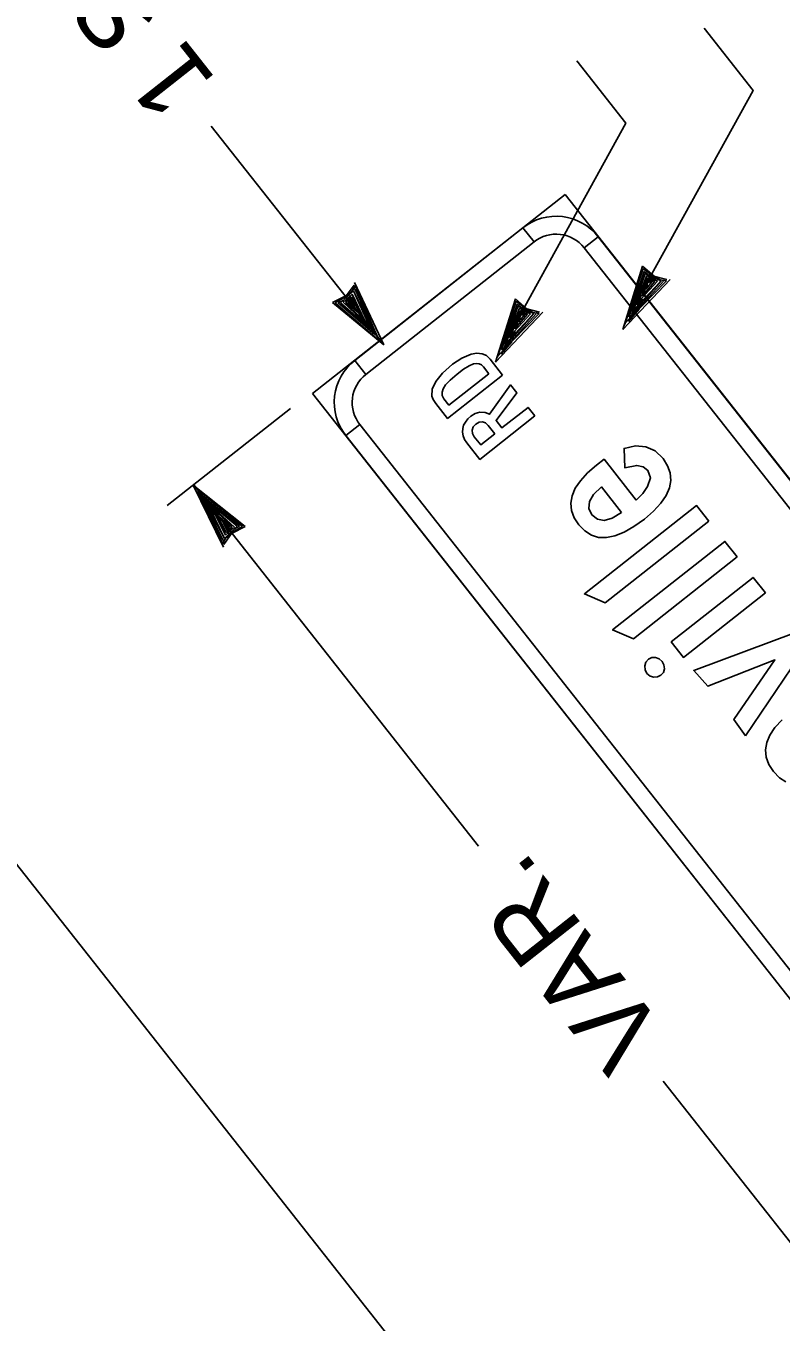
# Model space of a CAD drawing. Extents: x 672438 to 673763, y 1673171 to 1675010.
# Drawn here: x 673288.4 to 673330.7, y 1674719.6 to 1674792.2 of the extents above; entities that cross this region are included whole.
import ezdxf

# ---------------------------------------------------------------- set-up
doc = ezdxf.new("R2010")
doc.units = 0
for name, color, linetype in [('61', 7, 'Continuous'), ('C-ANNO-SYMB', 7, 'Continuous'), ('Level 1', 7, 'Continuous')]:
    doc.layers.add(name, color=color, linetype=linetype)

msp = doc.modelspace()

# ---------------------------------------------------------------- linework, layer by layer
at = {"layer": '61'}
msp.add_lwpolyline([(673330.593, 1674691.063), (673257.062, 1674784.333), (673234.11, 1674766.239), (673307.64, 1674672.968)], close=True, dxfattribs=at)
at = {"layer": 'C-ANNO-SYMB'}
for p, q in [((673318.61, 1674782.748), (673304.474, 1674771.604)), ((673318.61, 1674782.748), (673359.471, 1674730.917)), ((673316.254, 1674780.891), (673316.873, 1674780.105)), ((673319.682, 1674779.773), (673320.467, 1674780.392)), ((673307.449, 1674772.676), (673306.83, 1674773.461)), ((673304.474, 1674771.604), (673345.335, 1674719.774)), ((673306.332, 1674769.248), (673307.117, 1674769.867))]:
    msp.add_line(p, q, dxfattribs=at)
for points in [[(673316.873, 1674780.105), (673307.449, 1674772.676), (673306.83, 1674773.461), (673316.254, 1674780.891), (673316.873, 1674780.105), (673316.873, 1674780.105)], [(673356.828, 1674732.654), (673319.682, 1674779.773), (673320.467, 1674780.392), (673357.613, 1674733.273), (673356.828, 1674732.654), (673356.828, 1674732.654)], [(673307.117, 1674769.867), (673344.263, 1674722.749), (673343.478, 1674722.13), (673306.332, 1674769.248), (673307.117, 1674769.867), (673307.117, 1674769.867)], [(673326.66, 1674764.461), (673325.974, 1674765.33), (673319.692, 1674760.377), (673320.854, 1674759.883)], [(673328.245, 1674762.45), (673327.559, 1674763.32), (673321.277, 1674758.367), (673322.439, 1674757.873)], [(673329.83, 1674760.44), (673329.144, 1674761.309), (673324.553, 1674757.69), (673325.239, 1674756.821)], [(673328.706, 1674752.423), (673332.141, 1674757.508), (673331.568, 1674758.235), (673325.816, 1674756.089), (673326.6, 1674755.207), (673330.366, 1674756.681), (673328.07, 1674753.342)], [(673323.98, 1674755.828), (673324.115, 1674755.986), (673324.171, 1674756.189), (673324.149, 1674756.402), (673324.045, 1674756.596), (673323.879, 1674756.748), (673323.678, 1674756.824), (673323.472, 1674756.817), (673323.279, 1674756.717), (673323.137, 1674756.552), (673323.073, 1674756.346), (673323.093, 1674756.129), (673323.199, 1674755.929), (673323.368, 1674755.78), (673323.577, 1674755.714), (673323.792, 1674755.729)]]:
    msp.add_lwpolyline(points, close=True, dxfattribs=at)
for points in [[(673315.117, 1674772.641), (673314.41, 1674773.538), (673314.21, 1674773.727), (673313.965, 1674773.833), (673313.679, 1674773.859), (673313.347, 1674773.804), (673312.83, 1674773.592), (673312.304, 1674773.243), (673311.746, 1674772.748), (673311.367, 1674772.285), (673311.169, 1674771.857), (673311.15, 1674771.463), (673311.226, 1674771.274), (673311.373, 1674771.054), (673312.037, 1674770.212), (673315.117, 1674772.641)], [(673314.34, 1674772.713), (673312.112, 1674770.957), (673311.828, 1674771.318), (673311.738, 1674771.489), (673311.723, 1674771.674), (673311.784, 1674771.874), (673311.921, 1674772.089), (673312.172, 1674772.353), (673312.576, 1674772.694), (673312.925, 1674772.969), (673313.24, 1674773.164), (673313.481, 1674773.267), (673313.647, 1674773.292), (673313.794, 1674773.271), (673313.926, 1674773.205), (673314.039, 1674773.095), (673314.34, 1674772.713)], [(673316.925, 1674770.348), (673316.544, 1674770.831), (673315.078, 1674769.675), (673314.753, 1674770.086), (673315.902, 1674771.645), (673315.554, 1674772.087), (673314.388, 1674770.443), (673314.13, 1674770.549), (673313.846, 1674770.56), (673313.583, 1674770.487), (673313.336, 1674770.339), (673313.161, 1674770.18), (673313.027, 1674770.009), (673312.933, 1674769.829), (673312.879, 1674769.64), (673312.868, 1674769.437), (673312.905, 1674769.236), (673312.988, 1674769.037), (673313.118, 1674768.841), (673313.845, 1674767.919), (673316.925, 1674770.348)], [(673314.672, 1674769.355), (673313.887, 1674768.736), (673313.53, 1674769.188), (673313.433, 1674769.368), (673313.412, 1674769.557), (673313.474, 1674769.737), (673313.615, 1674769.892), (673313.806, 1674770.003), (673313.983, 1674770.028), (673314.15, 1674769.968), (673314.304, 1674769.822), (673314.672, 1674769.355)], [(673322.596, 1674765.64), (673320.793, 1674767.928), (673320.368, 1674767.593), (673319.868, 1674767.156), (673319.47, 1674766.724), (673319.186, 1674766.298), (673319.006, 1674765.877), (673318.939, 1674765.46), (673318.978, 1674765.05), (673319.129, 1674764.645), (673319.383, 1674764.249), (673319.716, 1674763.908), (673320.084, 1674763.674), (673320.489, 1674763.55), (673320.927, 1674763.537), (673321.407, 1674763.632), (673321.918, 1674763.836), (673322.467, 1674764.149), (673323.053, 1674764.572), (673323.572, 1674765.02), (673323.98, 1674765.461), (673324.278, 1674765.895), (673324.462, 1674766.321), (673324.539, 1674766.74), (673324.502, 1674767.155), (673324.355, 1674767.563), (673324.096, 1674767.961), (673323.651, 1674768.39), (673323.14, 1674768.628), (673322.563, 1674768.676), (673321.918, 1674768.531), (673321.955, 1674767.451), (673322.628, 1674767.579), (673322.985, 1674767.507), (673323.25, 1674767.295), (673323.388, 1674766.892), (673323.231, 1674766.392), (673322.965, 1674766.008), (673322.596, 1674765.64)], [(673321.77, 1674764.949), (673321.253, 1674764.627), (673320.803, 1674764.499), (673320.422, 1674764.562), (673320.109, 1674764.818), (673319.941, 1674765.172), (673319.972, 1674765.552), (673320.208, 1674765.952), (673320.643, 1674766.377), (673321.77, 1674764.949)], [(673330.764, 1674753.335), (673330.367, 1674752.902), (673330.082, 1674752.476), (673329.902, 1674752.056), (673329.835, 1674751.639), (673329.874, 1674751.228), (673330.025, 1674750.824), (673330.279, 1674750.427), (673330.613, 1674750.087), (673330.98, 1674749.853)]]:
    msp.add_lwpolyline(points, dxfattribs=at)
for centre, radius, start, end in [((673318.111, 1674778.535), 3, 38.2506, 128.25081), ((673318.111, 1674778.535), 2, 38.2506, 128.25081), ((673308.688, 1674771.106), 3, 128.25054, 218.25075), ((673308.688, 1674771.106), 2, 128.25054, 218.25075)]:
    msp.add_arc(centre, radius, start, end, dxfattribs=at)
at = {"layer": 'Level 1'}
for p, q in [((673308.457, 1674774.332), (673298.799, 1674786.583)), ((673321.838, 1674775.197), (673322.954, 1674778.747)), ((673321.956, 1674775.495), (673322.991, 1674778.602)), ((673322.184, 1674775.879), (673323.049, 1674778.444)), ((673322.374, 1674776.192), (673323.098, 1674778.322)), ((673322.954, 1674778.747), (673323.594, 1674778.18)), ((673322.991, 1674778.602), (673323.513, 1674778.197)), ((673323.049, 1674778.444), (673323.271, 1674778.251)), ((673323.098, 1674778.322), (673323.984, 1674777.915)), ((673306.318, 1674777.021), (673306.805, 1674777.681)), ((673306.68, 1674777.324), (673306.874, 1674777.635)), ((673306.805, 1674777.681), (673306.737, 1674777.464)), ((673306.826, 1674777.828), (673308.457, 1674774.332)), ((673306.874, 1674777.635), (673308.106, 1674774.76)), ((673324.492, 1674777.996), (673321.838, 1674775.197)), ((673324.123, 1674777.892), (673321.983, 1674775.54)), ((673324.292, 1674777.916), (673322.1, 1674775.684)), ((673322.352, 1674776.051), (673323.184, 1674778.212)), ((673323.984, 1674777.915), (673322.352, 1674776.051)), ((673323.984, 1674777.915), (673322.374, 1674776.192)), ((673322.657, 1674776.665), (673323.185, 1674778.057)), ((673323.796, 1674777.906), (673322.657, 1674776.665)), ((673322.921, 1674777.056), (673323.198, 1674777.926)), ((673323.631, 1674777.884), (673322.921, 1674777.056)), ((673323.235, 1674778.09), (673323.036, 1674777.2)), ((673323.513, 1674777.891), (673323.128, 1674777.452)), ((673323.128, 1674777.452), (673323.253, 1674777.865)), ((673323.184, 1674778.212), (673323.796, 1674777.906)), ((673323.185, 1674778.057), (673323.631, 1674777.884)), ((673323.198, 1674777.926), (673323.513, 1674777.891)), ((673323.683, 1674777.973), (673323.235, 1674778.09)), ((673323.253, 1674777.865), (673323.353, 1674777.834)), ((673323.271, 1674778.251), (673323.984, 1674777.915)), ((673323.353, 1674777.834), (673323.683, 1674777.973)), ((673323.513, 1674778.197), (673324.309, 1674777.998)), ((673323.594, 1674778.18), (673323.931, 1674777.978)), ((673323.931, 1674777.978), (673324.292, 1674777.916)), ((673324.081, 1674777.978), (673324.123, 1674777.892)), ((673305.597, 1674776.713), (673306.365, 1674777.089)), ((673305.745, 1674776.692), (673306.318, 1674777.021)), ((673305.914, 1674776.685), (673306.177, 1674776.818)), ((673306.045, 1674776.684), (673306.758, 1674777.35)), ((673306.177, 1674776.818), (673306.758, 1674777.35)), ((673306.18, 1674776.723), (673306.695, 1674777.173)), ((673306.59, 1674777.093), (673306.311, 1674776.723)), ((673306.323, 1674776.664), (673306.652, 1674777.011)), ((673306.365, 1674777.089), (673306.68, 1674777.324)), ((673306.449, 1674776.626), (673306.601, 1674776.904)), ((673306.594, 1674776.735), (673306.59, 1674777.093)), ((673306.601, 1674776.904), (673306.861, 1674776.382)), ((673306.652, 1674777.011), (673307.149, 1674776.04)), ((673306.695, 1674777.173), (673307.41, 1674775.647)), ((673306.737, 1674777.464), (673306.832, 1674777.47)), ((673306.758, 1674777.35), (673307.74, 1674775.206)), ((673306.758, 1674777.35), (673307.862, 1674775.132)), ((673306.832, 1674777.47), (673308.195, 1674774.597)), ((673314.713, 1674773.367), (673315.83, 1674776.917)), ((673315.83, 1674776.917), (673316.469, 1674776.35)), ((673322.836, 1674777.015), (673322.624, 1674776.561)), ((673322.624, 1674776.561), (673322.956, 1674776.912)), ((673323.036, 1674777.2), (673322.836, 1674777.015)), ((673308.457, 1674774.332), (673305.597, 1674776.713)), ((673308.226, 1674774.554), (673305.745, 1674776.692)), ((673307.958, 1674774.911), (673305.914, 1674776.685)), ((673307.74, 1674775.206), (673306.045, 1674776.684)), ((673307.862, 1674775.132), (673306.18, 1674776.723)), ((673306.311, 1674776.723), (673307.059, 1674776.201)), ((673307.41, 1674775.647), (673306.323, 1674776.664)), ((673307.149, 1674776.04), (673306.449, 1674776.626)), ((673306.527, 1674776.655), (673306.594, 1674776.735)), ((673306.861, 1674776.382), (673306.527, 1674776.655)), ((673307.059, 1674776.201), (673307.154, 1674775.946)), ((673317.368, 1674776.167), (673314.713, 1674773.367)), ((673314.831, 1674773.666), (673315.866, 1674776.772)), ((673317.167, 1674776.086), (673314.976, 1674773.854)), ((673315.06, 1674774.049), (673315.924, 1674776.614)), ((673315.228, 1674774.222), (673316.06, 1674776.382)), ((673316.86, 1674776.086), (673315.228, 1674774.222)), ((673315.25, 1674774.363), (673315.973, 1674776.492)), ((673316.86, 1674776.086), (673315.25, 1674774.363)), ((673315.532, 1674774.835), (673316.06, 1674776.227)), ((673315.797, 1674775.226), (673316.073, 1674776.096)), ((673315.866, 1674776.772), (673316.388, 1674776.368)), ((673316.11, 1674776.26), (673315.912, 1674775.371)), ((673315.924, 1674776.614), (673316.147, 1674776.421)), ((673315.973, 1674776.492), (673316.86, 1674776.086)), ((673316.06, 1674776.382), (673316.672, 1674776.076)), ((673316.06, 1674776.227), (673316.506, 1674776.054)), ((673316.073, 1674776.096), (673316.388, 1674776.062)), ((673316.559, 1674776.143), (673316.11, 1674776.26)), ((673316.147, 1674776.421), (673316.86, 1674776.086)), ((673316.229, 1674776.004), (673316.559, 1674776.143)), ((673316.388, 1674776.368), (673317.184, 1674776.168)), ((673316.469, 1674776.35), (673316.806, 1674776.148)), ((673316.806, 1674776.148), (673317.167, 1674776.086)), ((673316.957, 1674776.148), (673316.999, 1674776.062)), ((673322.166, 1674775.642), (673322.759, 1674776.327)), ((673322.759, 1674776.327), (673322.184, 1674775.879)), ((673316.999, 1674776.062), (673314.859, 1674773.711)), ((673316.672, 1674776.076), (673315.532, 1674774.835)), ((673315.912, 1674775.371), (673315.712, 1674775.186)), ((673316.506, 1674776.054), (673315.797, 1674775.226)), ((673316.388, 1674776.062), (673316.003, 1674775.623)), ((673316.003, 1674775.623), (673316.129, 1674776.035)), ((673316.129, 1674776.035), (673316.229, 1674776.004)), ((673315.712, 1674775.186), (673315.5, 1674774.731)), ((673315.5, 1674774.731), (673315.831, 1674775.082)), ((673315.042, 1674773.813), (673315.634, 1674774.497)), ((673315.634, 1674774.497), (673315.06, 1674774.049)), ((673303.242, 1674770.774), (673296.338, 1674765.331)), ((673299.485, 1674763.008), (673297.782, 1674766.469)), ((673297.782, 1674766.469), (673300.69, 1674764.148)), ((673313.772, 1674746.255), (673297.816, 1674766.496)), ((673298.141, 1674766.049), (673298.018, 1674766.251)), ((673298.018, 1674766.251), (673300.542, 1674764.166)), ((673299.471, 1674763.365), (673298.049, 1674766.209)), ((673298.049, 1674766.209), (673298.079, 1674766.002)), ((673298.079, 1674766.002), (673298.504, 1674765.203)), ((673299.433, 1674763.2), (673298.141, 1674766.049)), ((673298.504, 1674765.203), (673298.293, 1674765.9)), ((673298.293, 1674765.9), (673300.373, 1674764.169)), ((673299.544, 1674763.487), (673298.393, 1674765.681)), ((673298.393, 1674765.681), (673300.108, 1674764.126)), ((673299.544, 1674763.487), (673298.517, 1674765.61)), ((673298.517, 1674765.61), (673300.242, 1674764.167)), ((673299.118, 1674764.882), (673298.77, 1674765.244)), ((673298.77, 1674765.244), (673298.978, 1674764.808)), ((673299.602, 1674763.666), (673298.856, 1674765.176)), ((673298.856, 1674765.176), (673299.964, 1674764.181)), ((673299.219, 1674764.629), (673299.118, 1674764.882)), ((673299.642, 1674763.828), (673299.125, 1674764.788)), ((673299.125, 1674764.788), (673299.837, 1674764.217)), ((673299.977, 1674764.123), (673299.219, 1674764.629)), ((673299.691, 1674763.936), (673299.42, 1674764.453)), ((673299.42, 1674764.453), (673299.76, 1674764.187)), ((673299.977, 1674763.825), (673299.503, 1674763.155)), ((673300.242, 1674764.167), (673299.544, 1674763.487)), ((673300.113, 1674764.031), (673299.544, 1674763.487)), ((673300.108, 1674764.126), (673299.602, 1674763.666)), ((673299.931, 1674763.756), (673299.621, 1674763.514)), ((673299.964, 1674764.181), (673299.642, 1674763.828)), ((673299.837, 1674764.217), (673299.691, 1674763.936)), ((673299.76, 1674764.187), (673299.695, 1674764.105)), ((673299.695, 1674764.105), (673299.706, 1674763.747)), ((673299.706, 1674763.747), (673299.977, 1674764.123)), ((673300.69, 1674764.148), (673299.931, 1674763.756)), ((673300.542, 1674764.166), (673299.977, 1674763.825)), ((673300.373, 1674764.169), (673300.113, 1674764.031)), ((673299.621, 1674763.514), (673299.433, 1674763.2)), ((673299.567, 1674763.374), (673299.471, 1674763.365)), ((673338.711, 1674714.552), (673324.096, 1674733.09))]:
    msp.add_line(p, q, dxfattribs=at)
for points in [[(673322.975, 1674777.405), (673329.137, 1674788.581), (673326.392, 1674792.064)], [(673315.851, 1674775.575), (673322.013, 1674786.751), (673319.267, 1674790.234)]]:
    msp.add_lwpolyline(points, dxfattribs=at)

# ---------------------------------------------------------------- texts
for s, p in [('1 SIGN REQUIRED', (673299.156, 1674789.122)), ('VAR.', (673324.357, 1674735.81))]:
    msp.add_text(s, height=4.2, rotation=128.25054, dxfattribs=at).set_placement(p)

doc.saveas('drawing.dxf')
